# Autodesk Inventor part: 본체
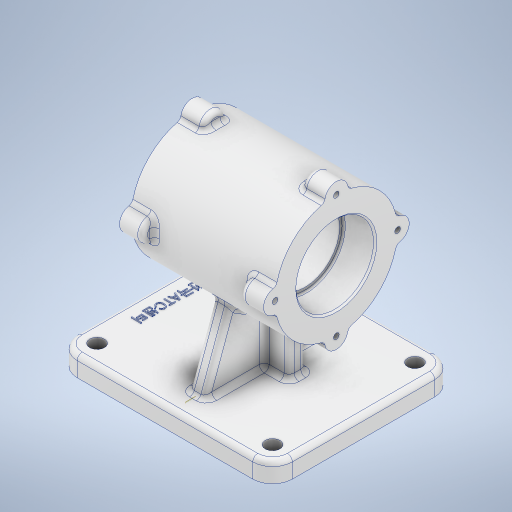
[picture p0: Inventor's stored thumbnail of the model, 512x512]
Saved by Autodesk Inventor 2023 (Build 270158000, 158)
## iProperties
Created: 2023-08
Part Number: 본체
Material: 알루미늄 6061
Document SubType Name: Modeling
Designer: asung
Density: 2.7 g/cm^3
Appearance: 알루미늄 - 평지
Author: asung
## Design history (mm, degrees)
sketch "스케치1"
  geometry: L1 (53, -55)-(-53, -55); L2 (-65, -43)-(-65, 43); L3 (-53, 55)-(53, 55); L4 (65, 43)-(65, -43); L5 (65, -55)-(-65, 55); L6 (-65, -55)-(65, 55); C1 r 4.5 at (53, -43); C2 r 4.5 at (53, 43); C3 r 4.5 at (-53, -43); C4 r 4.5 at (-53, 43); A1 r 12 centre (53, 43) between (65, 43) and (53, 55); A2 r 12 centre (53, -43) between (53, -55) and (65, -43); A3 r 12 centre (-53, -43) between (-65, -43) and (-53, -55); A4 r 12 centre (-53, 43) between (-53, 55) and (-65, 43); 1 further point
  constraints: 12 end point, 8 centre point, 8 point on circle, 8 point on line, 8 tangent, 4 coincident, 3 equal radius, 2 midpoint, 2 parallel, 1 horizontal, 1 perpendicular
  dimensions: "d0" = 130 distance of L5.end L6.end; "d1" = 110 distance of L6.start L5.end; "d2" = 12 radius of A1; "d3" = 9 diameter of C1; "d4" = 9 diameter of C2; "d5" = 9 diameter of C3; "d6" = 9 diameter of C4
extrude "돌출1" new body sketch "스케치1" distance "d7" = 12; taper "d8" = 0 deg
node "작업 평면3"
sketch "스케치2"
  geometry: L1 (98, 12)-(98, 0) reference; L2 (98, 0)-(-12, 0) reference; L3 (-12, 0)-(-12, 12) reference; L4 (-12, 12)-(98, 12) reference; L5 (43, 0)-(43, 82); C1 r 37 at (43, 82)
  constraints: 2 end point, 1 centre point, 1 coincident, 1 vertical
  dimensions: "d11" = 82 distance of L5.start L5.end; "d12" = 37 radius of C1
extrude "돌출2" join sketch "스케치2" stored distance "d13" = 87; taper "d14" = 0 deg
sketch "스케치3"
  geometry: C1 r 37 at (0, 0) reference; 1 further point
hole "구멍1" sketch "스케치3" at (0, 0) diameter "d15" = 42; stored, may be unused: countersink angle "d19" = 90 deg, drill point angle "d21" = 0 deg; dims "d16" = 10, "d17" = 47, "d18" = 19, "d20" = 87
sketch "스케치4"
  geometry: C1 r 37 at (0, 0) reference; 2 further points
  constraints: 1 coincident
hole "구멍2" sketch "스케치4" at (0, 0) diameter "d22" = 42; stored, may be unused: countersink angle "d26" = 90 deg, drill point angle "d28" = 0 deg; dims "d23" = 6, "d24" = 47, "d25" = 19, "d27" = 87
chamfer "모따기1" distance "d29" = 1; stored, may be unused: second distance "d30" = 2, angle "d31" = 45 deg
fillet "모깎기1" dims "d32" = 1
sketch "스케치5"
  geometry: C1 r 24.5 at (0, 0) reference; C2 r 7 at (0, 37); 2 further points
  constraints: 1 centre point, 1 vertical alignment, 1 other
  dimensions: "d33" = 7 radius of C2
extrude "돌출3" join sketch "스케치5" distance "d34" = 14; taper "d35" = 0 deg
fillet "모깎기2" dims "d36" = 3
fillet "모깎기3" dims "d37" = 3
node "작업 평면4"
sketch "스케치6"
  geometry: C1 r 24.5 at (43, 82) reference; C2 r 37 at (43, 82); A1 r 37 centre (43, 82) between (78.863, 91.104) and (52.104, 117.863) reference; A2 r 3 centre (52.842, 120.77) between (49.889, 120.239) and (52.104, 117.863) reference; A3 r 7 centre (43, 119) between (49.889, 120.239) and (36.111, 120.239) reference; A4 r 3 centre (33.158, 120.77) between (33.896, 117.863) and (36.111, 120.239) reference; A5 r 37 centre (43, 82) between (33.896, 117.863) and (7.137, 91.104) reference; A6 r 3 centre (4.23, 91.842) between (4.761, 88.889) and (7.137, 91.104) reference; A7 r 7 centre (6, 82) between (4.761, 88.889) and (4.761, 75.111) reference; A8 r 3 centre (4.23, 72.158) between (7.137, 72.896) and (4.761, 75.111) reference; A9 r 37 centre (43, 82) between (7.137, 72.896) and (33.896, 46.138) reference; A10 r 3 centre (33.158, 43.23) between (36.111, 43.761) and (33.896, 46.138) reference; A11 r 7 centre (43, 45) between (36.111, 43.761) and (49.889, 43.761) reference; A12 r 3 centre (52.842, 43.23) between (52.104, 46.138) and (49.889, 43.761) reference; A13 r 37 centre (43, 82) between (52.104, 46.138) and (78.863, 72.896) reference; A14 r 3 centre (81.77, 72.158) between (81.239, 75.111) and (78.863, 72.896) reference; A15 r 7 centre (80, 82) between (81.239, 75.111) and (81.239, 88.889) reference; A16 r 3 centre (81.77, 91.842) between (78.863, 91.104) and (81.239, 88.889) reference; 2 further points
  constraints: 2 coincident, 1 centre point
  dimensions: "d41" = 37 radius of C2
hole "구멍3" sketch "스케치6" at (43, 119) diameter "d42" = 3.45873; stored, may be unused: countersink angle "d46" = 90 deg, drill point angle "d48" = 118 deg; dims "d43" = 8, "d44" = 47, "d45" = 19, "d47" = 10
sketch "스케치7"
  geometry: L1 (-15, 5)-(25, 5); L2 (25, 5)-(25, -5); L3 (25, -5)-(-15, -5); L4 (-15, -5)-(-15, 5); L5 (-65, 43)-(-65, -43) reference; 4 further points
  constraints: 8 end point, 3 midpoint, 2 parallel, 1 horizontal, 1 perpendicular
  dimensions: "d52" = 40 distance of L2.end L3.end; "d53" = 10 distance of L1.end L2.end; "d54" = 70 distance from line of L5 point (5, 5); "d55" = 0 vertical distance of point (-65, 0) point (-15, 0)
extrude "돌출4" join sketch "스케치7" stored distance "d56" = 14; taper "d57" = 0 deg
sketch "스케치8"
  geometry: L1 (98, 12)-(98, 0) reference; L2 (98, 0)-(-12, 0) reference; L3 (-12, 0)-(-12, 12) reference; L4 (-12, 12)-(38, 12) reference; L5 (38, 12)-(38, 45.339) reference; L6 (48, 45.339)-(48, 12) reference; L7 (48, 12)-(98, 12) reference; L8 (81.5, 12)-(90.5, 12) reference; L9 (84, 12)-(68.336, 55.036); L10 (-4.5, 12)-(4.5, 12) reference; L11 (2, 12)-(17.664, 55.036); C1 r 21 at (43, 82) reference; A1 r 37 centre (43, 82) between (48, 45.339) and (38, 45.339) reference; 1 further point
  constraints: 4 end point, 2 point on circle, 2 point on line
  dimensions: "d58" = 14 distance from line of L1 L9.start; "d59" = 14 distance from line of L3 L11.start; "d60" = 110 deg angle of L7 L9; "d61" = 110 deg angle of L4 L11
  node "절단 모서리 투영2"
feature "리브1" dims "d62" = 1, "d63" = 10, "d64" = 0, "d65" = 0, "d66" = 1, "d67" = 1
feature "리브2" dims "d68" = 1, "d69" = 10, "d70" = 0, "d71" = 0, "d72" = 1, "d73" = 1
fillet "모깎기4" dims "d74" = 3
fillet "모깎기5" dims "d75" = 3
sketch "스케치9"
  geometry: L1 (-62, -43)-(-62, 43) reference; L2 (3, -43.101)-(7, -43.101) reference; 4 further points
  constraints: 2 midpoint, 1 horizontal alignment, 1 other
  dimensions: "d76" = 58 horizontal distance of point (5, -43.101) point (-53, 0)
feature "엠보싱1" sketch "스케치9" dims "d0" = 130, "d1" = 110, "d2" = 12, "d3" = 9, "d4" = 9, "d5" = 9, "d6" = 9, "d77" = 0.5, "d78" = 0
feature "Σ耀Υ耀Χ耀Ω耀Ϋ耀έ耀ί耀α耀" dims "d0" = 130, "d1" = 110, "d2" = 12, "d3" = 9, "d4" = 9, "d5" = 9, "d6" = 9, "d7" = 12, "d8" = 0, "d10" = -70, "d11" = 82, "d12" = 37, "d13" = 87, "d14" = 0, "d15" = 42, "d16" = 10, "d17" = 47, "d18" = 19, "d19" = 90 deg, "d20" = 87, "d21" = 0, "d22" = 42, "d23" = 6, "d24" = 47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
node "솔리드1"
pattern_circular "원형 패턴1" dims angle "d39" = 360 deg
mirror "미러1"
pattern_circular "원형 패턴2" dims angle "d50" = 360 deg
mirror "미러2"
node "투영된 루프1"
node "투영된 루프2"
node "투영된 루프3"
node "절단 모서리 투영1"
feature "A9D066F2-1C7D-4E18-AEED-F7BC21143FA4" dims "d15" = 42, "d16" = 10, "d17" = 47, "d18" = 19, "d19" = 90 deg, "d20" = 87, "d21" = 0
